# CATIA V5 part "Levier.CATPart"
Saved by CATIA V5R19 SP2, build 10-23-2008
Part number: Levier
Bounding box of the stored display mesh (mm): x -2 to 1, y -42.426 to 4.316, z -23.82 to 5.477
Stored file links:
  G:\EU_thinkMotion\CFAO_2010\MMS_groupe3\MMS_groupe3\A reprendre\lletoffe\lletoffe_Thinkmotion_CFAO\Modèle Catia\Levier.CATPart
  G:\EU_thinkMotion\CFAO_2010\MMS_groupe3\MMS_groupe3\A reprendre\lletoffe\lletoffe_Thinkmotion_CFAO\Modèle Catia\levier.CATPart
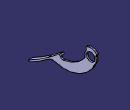
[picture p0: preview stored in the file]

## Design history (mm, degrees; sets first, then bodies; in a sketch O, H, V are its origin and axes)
Parameters
  Epaisseur = 1 mm
Set1
  Point1: (0, 0, 0)
  Point2: (1, 0, 0)
  Line1: type PtPt, FirstPoint Point1, SecondPoint Point2, Start 10, End 10
  Plane1: type Offset, RefPlane yz-plane, Offset 1 {= Epaisseur}
  Plane2: type Offset, RefPlane yz-plane, Offset 2 {= 2*Epaisseur}, reversed
  Sketch1 on yz-plane, origin (0, 0, 0), H (0, 1, 0), V (0, 0, 1)
    arc A1 centre (0, 0) radius 4 from (-2.9114, 2.7429) to (-3.9144, -0.8231) ccw
    arc A2 centre (-6.8502, -1.4404) radius 3 from (-4.5174, -3.3267) to (-3.9144, -0.8231) ccw
    point P1 (3.6883, 1.5481)
    point P2 (3.6883, 1.5481)
    arc A3 centre (0, 0) radius 5.5 from (4.2062, 3.5437) to (-2.9863, 4.6187) ccw
    arc A4 centre (-2.7148, 4.1988) radius 0.5 from (-2.9863, 4.6187) to (-3.1341, 3.9265) ccw
    point P3 (-2.9863, 4.6187)
    point P4 (-2.9863, 4.6187)
    line L1 (-3.1341, 3.9265) -> (-2.8449, 3.4811)
    arc A5 centre (-3.3481, 3.1543) radius 0.6 from (-2.9114, 2.7429) to (-2.8449, 3.4811) ccw
    point P5 (-2.8449, 3.4811)
    point P6 (-2.8449, 3.4811)
    point P7 (-2.9114, 2.7429)
    point P8 (-2.9114, 2.7429)
    point P9 (-4.5174, -3.3267)
    point P10 (-4.5174, -3.3267)
    arc A6 centre (-21.6243, 10.5064) radius 22 from (-18.7348, -11.303) to (-4.5174, -3.3267) ccw
    point P11 (-18.7348, -11.303)
    point P12 (-18.7348, -11.303)
    arc A7 centre (-18.9975, -9.3204) radius 2 from (-20.615, -10.4968) to (-18.7348, -11.303) ccw
    point P13 (-20.615, -10.4968)
    point P14 (-20.615, -10.4968)
    line L2 (-21.4973, -9.2837) -> (-20.615, -10.4968)
    line L3 (-21.4973, -9.2837) -> (-29.1801, -14.8716)
    point P15 (3.7246, -1.4586)
    point P16 (3.7246, -1.4586)
    arc A8 centre (0, 0) radius 4 from (3.7246, -1.4586) to (3.5862, 1.7718) ccw
    arc A9 centre (-17.6917, 6.9284) radius 23 from (-24.7979, -14.9463) to (3.7246, -1.4586) ccw
    point P17 (-3.9144, -0.8231)
    point P18 (-24.7979, -14.9463)
    point P19 (-24.7979, -14.9463)
    arc A10 centre (-26.0337, -18.7506) radius 4 from (-24.7979, -14.9463) to (-28.3946, -15.5216) ccw
    point P20 (-29.1801, -14.8716)
    point P21 (-29.1801, -14.8716)
    arc A11 centre (-88, 66) radius 100 from (-42.426, -23.0113) to (-29.1801, -14.8716) ccw
    point P22 (-28.3946, -15.5216)
    point P23 (-28.3946, -15.5216)
    arc A12 centre (-88, 66) radius 100.988 from (-41.8378, -23.82) to (-28.3946, -15.5216) ccw
    line L4 (-42.426, -23.0113) -> (-41.8378, -23.82)
    point P24 (-41.8378, -23.82)
    point P25 (-41.8378, -23.82)
    point P26 (-88, 66)
    point P27 (-88, 66)
    point P28 (3.7384, 2.4972)
    point P29 (3.7384, 2.4972)
    line L5 (4.1452, 2.8386) -> (3.7384, 2.4972)
    arc A13 centre (4.1241, 2.0376) radius 0.6 from (3.7384, 2.4972) to (3.5862, 1.7718) ccw
    point P30 (4.1452, 2.8386)
    point P31 (4.1452, 2.8386)
    arc A14 centre (3.8238, 3.2216) radius 0.5 from (4.1452, 2.8386) to (4.2062, 3.5437) ccw
    point P32 (4.2062, 3.5437)
    point P33 (4.2062, 3.5437)
    point P34 (3.5862, 1.7718)
    point P35 (3.5862, 1.7718)
    point P36 (0, 0)
    construction line L6 through (-24.6479, 0) direction (1, 0)
    construction line L7 through (0, -19.8447) direction (0, 1)
    point P53 (0, 0)
    reference projected point E1 (0, 0) from Line1
    circle A15 centre (0, 0) radius 3
    point P54 (0, 0)
    radius A4 = 0.5
    length L1 = 0.531
    radius A2 = 3
    length L3 = 9.5
    length L2 = 1.5
    radius A7 = 2
    distance P17 L3 = 3.5
    length L4 = 1
    distance L4 L2 = 25
    radius A11 = 100
    radius A10 = 4
    distance L2 P18 = 6
    length L5 = 0.531
    radius A14 = 0.5
    radius A13 = 0.6
    distance P15 L2 = 25
    radius A6 = 22
    radius A9 = 23
    distance L7 P27 = 88
    distance L6 P27 = 66
    radius A1 = 4
    radius A8 = 4
    radius A3 = 5.5
    angle L5 L6 = 40
    angle L1 L6 = 57
    radius A5 = 0.6
    radius A15 = 3
    tangency: A2 A1, A4 A3, L1 A4, A5 L1, A1 A5, A6 A2, A7 A6, L2 A7, A9 A8, A10 A9, A11 L3, A12 A10, A13 L5, L5 A14, A14 A3, A13 A8
    coincidence: P1 A1, P2 P1, P4 P3, P6 P5, P8 P7, P10 P9, P12 P11, P14 P13, P16 P15, P19 P18, P21 P20, P23 P22, P25 P24, P27 P26, P29 P28, P31 P30, P33 P32, P35 P34, P36 L6, P36 L7, P53 L7, P53 L6, P53 E1, P54 L6, P54 L7
    perpendicularity: L3 L2, L4 L3, L6 L7
    vertical: L7 V
    concentricity: A8 A15
  Sketch2 on yz-plane, origin (0, 0, 0), H (0, 1, 0), V (0, 0, 1)
    point P1 (-20.9161, -10.0827)
    line L1 (-20.9161, -10.0827) -> (-21.4973, -9.2837)
    line L2 (-21.4973, -9.2837) -> (-29.1801, -14.8716)
    arc A1 centre (-88, 66) radius 100 from (-29.1801, -14.8716) to (-42.426, -23.0113) cw
    line L3 (-42.426, -23.0113) -> (-41.8378, -23.82)
    point P7 (-20.9161, -10.0827)
    line L4 (-20.9161, -10.0827) -> (-28.5989, -15.6706)
    arc A2 centre (-88, 66) radius 100.988 from (-28.5989, -15.6706) to (-41.8378, -23.82) cw
    reference projected arc E1 centre (-88, 66) radius 100 from (-42.6244, -23.1126) to (-29.3604, -15.0024) ccw from Sketch1.A11
    reference projected line E2 (-42.4463, -22.9834) -> (-41.8581, -23.7921) from Sketch1.L4
    reference projected line E3 (-21.6774, -9.4147) -> (-29.3602, -15.0026) from Sketch1.L3
    reference projected line E4 (-20.6025, -10.5139) -> (-21.4848, -9.3008) from Sketch1.L2
    reference projected arc E5 centre (-88, 66) radius 100.988 from (-42.038, -23.9226) to (-28.5451, -15.6315) ccw from Sketch1.A12
    perpendicularity: L2 L1
    tangency: A1 L2, A2 L4
    coincidence: P7 L1, P7 P1, A1 E1, L3 E2, L2 E3, L1 E4, A2 E5
    parallelism: L4 L2
Body1 (main body)
  Pad1: profile Sketch1, direction (1, 0, 0), up to Plane1
  Pad2: profile Sketch2, direction (1, 0, 0), up to Plane2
